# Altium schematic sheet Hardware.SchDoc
size 431 x 279 mm; Date: Not shown in title block; ApprovedBy: Not shown in title block; CheckedBy: Not shown in title block; Author: Not shown in title block; CompanyName: Not shown in title block; DrawnBy: X.Gong; Engineer: Not shown in title block; Organization: Not shown in title block; Address1: Not shown in title block; Address2: Not shown in title block; Address3: Not shown in title block; Address4: Not shown in title block; DocumentNumber: 3; Revision: Use project parameter SCH_Rev; SheetNumber: 3; SheetTotal: 3; PageSetup: Record=PageOptions¦CenterHorizontal=True¦CenterVertical=True¦PrintScale=1.00¦XCorrection=1.00¦YCorrection=1.00¦PrintKind=0¦BorderSize=5000000¦LeftOffset=0¦BottomOffset=0¦Orientation=2¦PaperLength=1000¦PaperWidth=1000¦Scale=100¦PaperSource=15¦PrintQuality=600¦MediaType=1¦DitherType=10¦PaperKind=Letter¦PrintScaleMode=1
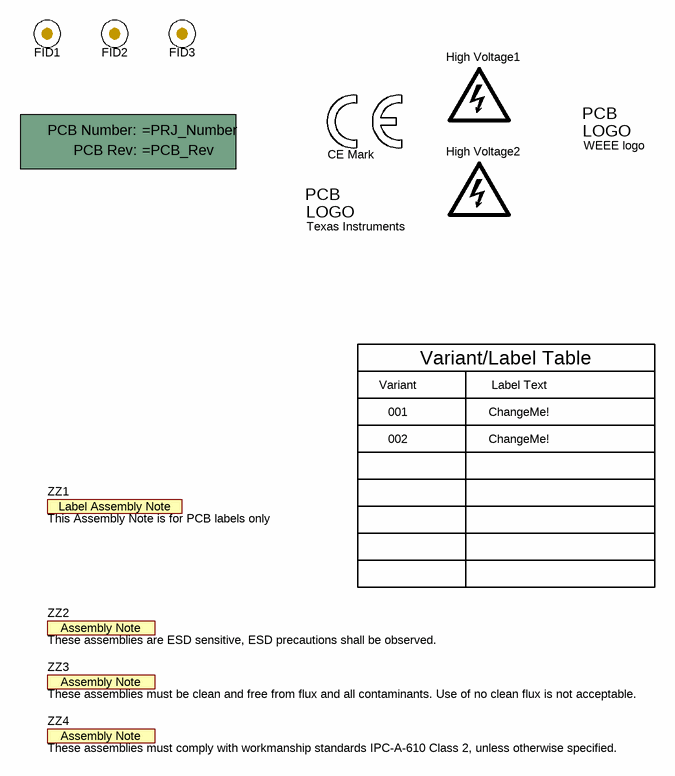
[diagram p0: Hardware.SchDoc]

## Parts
!PCB1  Printed Circuit Board  (value not drawn)  (mechanical)
FID1  Fiducial  [Fiducial10-20]  (value not drawn)
FID2  Fiducial  [Fiducial10-20]  (value not drawn)
FID3  Fiducial  [Fiducial10-20]  (value not drawn)
High_Voltage1  DANGER HIGH VOLTAGE  [IEC_HighVoltage_Small]  (value not drawn)  (no BOM)
High_Voltage2  DANGER HIGH VOLTAGE  [IEC_HighVoltage_Small]  (value not drawn)  (no BOM)
Logo1  CE Mark  [CE_Mark_5mm]  (no BOM)
Logo2  WEEE logo  [WEEE_Minimum]  (no BOM)
Logo3  Texas Instruments  [TI_Stacked_Overlay_Small]  (no BOM)
ZZ1  This Assembly Note is for PCB labels only  [AssemblyNoteLabel]  (no BOM)
ZZ2  These assemblies are ESD sensitive, ESD precautions shall be observed.  [AssemblyNote]  (no BOM)
ZZ3  These assemblies must be clean and free from flux and all contaminants. Use of no clean flux is not acceptable.  [AssemblyNote]  (no BOM)
ZZ4  These assemblies must comply with workmanship standards IPC-A-610 Class 2, unless otherwise specified.  [AssemblyNote]  (no BOM)

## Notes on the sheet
- Variant
- Variant/Label Table
- Label Text
- 001
- 002
- ChangeMe!

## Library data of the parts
!PCB1 = CMP-0003618-2: Manufacturer: Any
FID1-FID3 = CMP-0077181-1: Fiducial mark.  There is nothing to buy or mount.
High_Voltage1 High_Voltage2 = CMP-0074835-1: IEC 61010-1 High Voltage Warning; SymbolCreator: a0412235
Logo1 = CMP-0074844-1: SymbolCreator: a0412235
Logo2 = CMP-0074769-1
Logo3 = CMP-0074838-1: Texas Instrument Corporate Signature; SymbolCreator: a0412235; Lib Reference: TI_Logo; Library Reference: Logo
ZZ1 = CMP-0003616-3
ZZ2 = CMP-0077236-1
ZZ3 = CMP-0077237-1
ZZ4 = CMP-0077238-1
